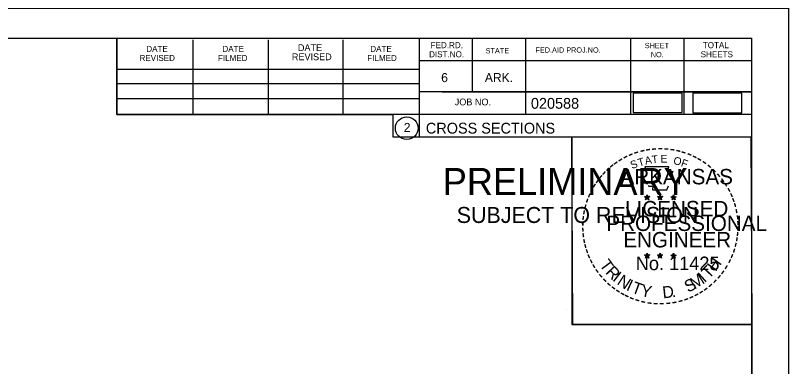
# Model space of a CAD drawing. Extents: x 1368968 to 1369915, y 377395 to 380381.
# Drawn here: x 1369814.5 to 1369914.7, y 378841.6 to 378887.1 of the extents above; entities that cross this region are included whole.
import ezdxf

# ---------------------------------------------------------------- set-up
doc = ezdxf.new("R2010")
doc.units = 0
for name, color, linetype in [('Default', 7, 'Continuous'), ('S_BRIDGE_ANNOT', 7, 'Continuous'), ('S_BUILDING_ANNOT', 7, 'Continuous'), ('S_CAL_CORNER', 7, 'Continuous'), ('S_DROP_INLET', 7, 'Continuous')]:
    doc.layers.add(name, color=color, linetype=linetype)

msp = doc.modelspace()

# ---------------------------------------------------------------- linework, layer by layer
at = {"layer": 'Default'}
for points in [[(1369894.57, 378874.54), (1369900.91, 378874.54), (1369900.91, 378877.06), (1369894.57, 378877.06)], [(1369902.32, 378874.51), (1369908.66, 378874.51), (1369908.66, 378877.03), (1369902.32, 378877.03)]]:
    msp.add_lwpolyline(points, close=True, dxfattribs=at)
at = {"layer": 'S_BRIDGE_ANNOT'}
for p, q in [((1369593.78, 378884.16), (1369909.96, 378884.16)), ((1369827.7, 378874.28), (1369827.7, 378884.16)), ((1369837.56, 378874.28), (1369837.56, 378883.96)), ((1369847.32, 378874.28), (1369847.32, 378883.96)), ((1369857, 378874.28), (1369857, 378883.96)), ((1369866.86, 378884.16), (1369866.86, 378871.36)), ((1369873.7, 378884.16), (1369873.7, 378877.22)), ((1369880.64, 378884.16), (1369880.64, 378874.28)), ((1369894.22, 378884.16), (1369894.22, 378874.28)), ((1369901.16, 378884.16), (1369901.16, 378874.28)), ((1369909.96, 378678.7), (1369909.96, 378884.16)), ((1369909.96, 378881.22), (1369866.86, 378881.22)), ((1369909.96, 378881.24), (1369909.96, 378881.24)), ((1369827.7, 378880.14), (1369866.86, 378880.14)), ((1369827.7, 378878.28), (1369866.86, 378878.28)), ((1369909.96, 378877.22), (1369866.86, 378877.22)), ((1369869.82, 378877.22), (1369909.96, 378877.22)), ((1369827.7, 378874.28), (1369827.7, 378876.34)), ((1369827.7, 378876.34), (1369866.86, 378876.34)), ((1369909.96, 378874.28), (1369827.7, 378874.28)), ((1369866.86, 378871.36), (1369909.96, 378871.36))]:
    msp.add_line(p, q, dxfattribs=at)
msp.add_circle((1369865.24, 378872.5), 1.47, dxfattribs=at)
at = {"layer": 'S_BUILDING_ANNOT'}
for p, q in [((1369896.04, 378863.62), (1369896.39, 378863.51)), ((1369896.04, 378863.62), (1369896.29, 378863.58)), ((1369896.04, 378863.62), (1369896.28, 378863.5)), ((1369896.17, 378863.21), (1369896.39, 378863.51)), ((1369896.39, 378863.87), (1369896.35, 378863.62)), ((1369896.39, 378863.51), (1369896.39, 378863.87)), ((1369896.39, 378863.87), (1369896.44, 378863.62)), ((1369896.74, 378863.62), (1369896.39, 378863.51)), ((1369896.6, 378863.21), (1369896.39, 378863.51)), ((1369896.74, 378863.62), (1369896.45, 378863.57)), ((1369896.6, 378863.21), (1369896.47, 378863.5)), ((1369896.74, 378863.62), (1369896.53, 378863.52)), ((1369897.71, 378863.62), (1369898.06, 378863.51)), ((1369897.71, 378863.62), (1369897.96, 378863.58)), ((1369897.71, 378863.62), (1369897.95, 378863.5)), ((1369897.84, 378863.21), (1369898.06, 378863.51)), ((1369898.06, 378863.87), (1369898.02, 378863.62)), ((1369898.06, 378863.51), (1369898.06, 378863.87)), ((1369898.06, 378863.87), (1369898.11, 378863.62)), ((1369898.41, 378863.62), (1369898.06, 378863.51)), ((1369898.27, 378863.21), (1369898.06, 378863.51)), ((1369898.41, 378863.62), (1369898.12, 378863.57)), ((1369898.27, 378863.21), (1369898.14, 378863.5)), ((1369898.41, 378863.62), (1369898.2, 378863.52)), ((1369899.48, 378863.61), (1369899.82, 378863.5)), ((1369899.48, 378863.61), (1369899.73, 378863.56)), ((1369899.48, 378863.61), (1369899.71, 378863.49)), ((1369899.61, 378863.2), (1369899.82, 378863.5)), ((1369899.82, 378863.86), (1369899.78, 378863.61)), ((1369899.82, 378863.5), (1369899.82, 378863.86)), ((1369899.82, 378863.86), (1369899.87, 378863.61)), ((1369900.17, 378863.61), (1369899.82, 378863.5)), ((1369900.04, 378863.2), (1369899.82, 378863.5)), ((1369900.17, 378863.61), (1369899.89, 378863.56)), ((1369900.04, 378863.2), (1369899.9, 378863.49)), ((1369900.17, 378863.61), (1369899.97, 378863.51)), ((1369896.17, 378863.21), (1369896.3, 378863.46)), ((1369896.17, 378863.21), (1369896.39, 378863.43)), ((1369896.6, 378863.21), (1369896.39, 378863.43)), ((1369897.84, 378863.21), (1369897.97, 378863.46)), ((1369897.84, 378863.21), (1369898.06, 378863.43)), ((1369898.27, 378863.21), (1369898.06, 378863.43)), ((1369899.61, 378863.2), (1369899.73, 378863.44)), ((1369899.61, 378863.2), (1369899.82, 378863.42)), ((1369900.04, 378863.2), (1369899.82, 378863.41)), ((1369896.04, 378856.05), (1369896.39, 378855.94)), ((1369896.04, 378856.05), (1369896.29, 378856)), ((1369896.04, 378856.05), (1369896.27, 378855.93)), ((1369896.17, 378855.64), (1369896.39, 378855.94)), ((1369896.17, 378855.64), (1369896.3, 378855.88)), ((1369896.17, 378855.64), (1369896.38, 378855.86)), ((1369896.39, 378856.3), (1369896.35, 378856.05)), ((1369896.6, 378855.64), (1369896.38, 378855.85)), ((1369896.39, 378855.94), (1369896.39, 378856.3)), ((1369896.39, 378856.3), (1369896.44, 378856.05)), ((1369896.73, 378856.05), (1369896.39, 378855.94)), ((1369896.6, 378855.64), (1369896.39, 378855.94)), ((1369896.73, 378856.05), (1369896.45, 378856)), ((1369896.6, 378855.64), (1369896.46, 378855.93)), ((1369896.73, 378856.05), (1369896.53, 378855.95)), ((1369897.71, 378856.05), (1369898.06, 378855.94)), ((1369897.71, 378856.05), (1369897.96, 378856)), ((1369897.71, 378856.05), (1369897.94, 378855.93)), ((1369897.84, 378855.64), (1369898.06, 378855.94)), ((1369897.84, 378855.64), (1369897.97, 378855.88)), ((1369897.84, 378855.64), (1369898.05, 378855.86)), ((1369898.06, 378856.3), (1369898.01, 378856.05)), ((1369898.27, 378855.64), (1369898.05, 378855.85)), ((1369898.06, 378855.94), (1369898.06, 378856.3)), ((1369898.06, 378856.3), (1369898.1, 378856.05)), ((1369898.4, 378856.05), (1369898.06, 378855.94)), ((1369898.27, 378855.64), (1369898.06, 378855.94)), ((1369898.4, 378856.05), (1369898.12, 378856)), ((1369898.27, 378855.64), (1369898.13, 378855.93)), ((1369898.4, 378856.05), (1369898.2, 378855.95)), ((1369899.47, 378856.04), (1369899.82, 378855.93)), ((1369899.47, 378856.04), (1369899.73, 378855.99)), ((1369899.47, 378856.04), (1369899.71, 378855.92)), ((1369899.61, 378855.63), (1369899.82, 378855.93)), ((1369899.61, 378855.63), (1369899.73, 378855.87)), ((1369899.61, 378855.63), (1369899.82, 378855.85)), ((1369899.82, 378856.29), (1369899.78, 378856.04)), ((1369899.82, 378855.93), (1369899.82, 378856.29)), ((1369899.82, 378856.29), (1369899.87, 378856.04)), ((1369900.17, 378856.04), (1369899.82, 378855.93)), ((1369900.04, 378855.63), (1369899.82, 378855.93)), ((1369900.04, 378855.63), (1369899.82, 378855.84)), ((1369900.17, 378856.04), (1369899.88, 378855.99)), ((1369900.04, 378855.63), (1369899.9, 378855.92)), ((1369900.17, 378856.04), (1369899.97, 378855.94))]:
    msp.add_line(p, q, dxfattribs=at)
for points in [[(1369896.08, 378867.5), (1369896.35, 378866.67)], [(1369899.59, 378866.58), (1369899.74, 378866.86), (1369899.05, 378866.84), (1369899.2, 378867.5), (1369896.08, 378867.5)], [(1369896.57, 378865.08), (1369896.57, 378864.99), (1369897.14, 378864.97), (1369897.08, 378864.5), (1369898.95, 378864.5), (1369899.15, 378865.03)], [(1369896.39, 378863.87), (1369896.6, 378863.21), (1369896.04, 378863.62), (1369896.74, 378863.62), (1369896.17, 378863.21), (1369896.39, 378863.87)], [(1369898.06, 378863.87), (1369898.27, 378863.21), (1369897.71, 378863.62), (1369898.41, 378863.62), (1369897.84, 378863.21), (1369898.06, 378863.87)], [(1369899.82, 378863.86), (1369900.04, 378863.2), (1369899.48, 378863.61), (1369900.17, 378863.61), (1369899.61, 378863.2), (1369899.82, 378863.86)], [(1369896.39, 378856.3), (1369896.6, 378855.64), (1369896.04, 378856.05), (1369896.73, 378856.05), (1369896.17, 378855.64), (1369896.39, 378856.3)], [(1369898.06, 378856.3), (1369898.27, 378855.64), (1369897.71, 378856.05), (1369898.4, 378856.05), (1369897.84, 378855.64), (1369898.06, 378856.3)], [(1369899.82, 378856.29), (1369900.04, 378855.63), (1369899.47, 378856.04), (1369900.17, 378856.04), (1369899.61, 378855.63), (1369899.82, 378856.29)]]:
    msp.add_lwpolyline(points, dxfattribs=at)
for centre, radius in [((1369896.39, 378863.51), 0.172), ((1369896.39, 378863.51), 0.145), ((1369896.39, 378863.51), 0.116), ((1369896.39, 378863.51), 0.0991), ((1369896.39, 378863.51), 0.0747), ((1369896.39, 378863.51), 0.0495), ((1369896.39, 378863.51), 0.0296), ((1369898.06, 378863.51), 0.172), ((1369898.06, 378863.51), 0.145), ((1369898.06, 378863.51), 0.116), ((1369898.06, 378863.51), 0.0991), ((1369898.06, 378863.51), 0.0747), ((1369898.06, 378863.51), 0.0495), ((1369898.06, 378863.51), 0.0296), ((1369899.82, 378863.5), 0.172), ((1369899.82, 378863.5), 0.145), ((1369899.82, 378863.5), 0.116), ((1369899.82, 378863.5), 0.0991), ((1369899.82, 378863.5), 0.0747), ((1369899.82, 378863.5), 0.0495), ((1369899.82, 378863.5), 0.0296), ((1369896.39, 378855.94), 0.172), ((1369896.39, 378855.94), 0.145), ((1369896.39, 378855.94), 0.116), ((1369896.39, 378855.94), 0.0991), ((1369896.39, 378855.94), 0.0747), ((1369896.39, 378855.94), 0.0495), ((1369896.39, 378855.94), 0.0296), ((1369898.05, 378855.94), 0.172), ((1369898.05, 378855.94), 0.145), ((1369898.05, 378855.94), 0.116), ((1369898.05, 378855.94), 0.0991), ((1369898.05, 378855.94), 0.0747), ((1369898.05, 378855.94), 0.0495), ((1369898.05, 378855.94), 0.0296), ((1369899.82, 378855.93), 0.172), ((1369899.82, 378855.93), 0.145), ((1369899.82, 378855.93), 0.116), ((1369899.82, 378855.93), 0.0991), ((1369899.82, 378855.93), 0.0747), ((1369899.82, 378855.93), 0.0495), ((1369899.82, 378855.93), 0.0296)]:
    msp.add_circle(centre, radius, dxfattribs=at)
at = {"layer": 'S_DROP_INLET'}
msp.add_line((1369885.99, 378848.91), (1369885.99, 378848.91), dxfattribs=at)
for points in [[(1369581.37, 378888.06), (1369914.71, 378888.06), (1369914.71, 378674.72), (1369581.37, 378674.72)], [(1369827.7, 378884.16), (1369827.7, 378874.28), (1369863.43, 378874.28), (1369863.43, 378871.36), (1369886.63, 378871.36), (1369886.63, 378847.03), (1369909.96, 378847.03), (1369909.96, 378678.7), (1369593.78, 378678.7), (1369593.78, 378884.16)], [(1369886.63, 378871.36), (1369909.84, 378871.36), (1369909.96, 378847.03), (1369886.75, 378847.03)]]:
    msp.add_lwpolyline(points, close=True, dxfattribs=at)

# ---------------------------------------------------------------- texts
at = {"layer": 'S_BRIDGE_ANNOT'}
for s, height, p in [('FED.RD.', 0.782, (1369868.34, 378882.88)), ('SHEET', 0.684, (1369896.08, 378882.88)), ('TOTAL', 0.782, (1369903.6, 378882.88)), ('DATE', 0.782, (1369831.5, 378882.4)), ('DATE', 0.782, (1369841.36, 378882.4)), ('DATE', 0.879, (1369851.14, 378882.5)), ('DATE', 0.782, (1369860.52, 378882.4)), ('DIST.NO.', 0.782, (1369868.14, 378881.7)), ('STATE', 0.684, (1369875.46, 378882.2)), ('FED.AID PROJ.NO.', 0.684, (1369881.92, 378882.3)), ('SHEETS', 0.782, (1369903.32, 378881.7)), ('REVISED', 0.782, (1369830.62, 378881.22)), ('FILMED', 0.782, (1369840.78, 378881.22)), ('REVISED', 0.879, (1369850.36, 378881.32)), ('FILMED', 0.782, (1369860.12, 378881.22)), ('NO.', 0.684, (1369896.86, 378881.7)), ('6', 1.17, (1369869.7, 378878.48)), ('ARK.', 1.172, (1369875.36, 378878.48)), ('JOB NO.', 0.879, (1369871.46, 378875.46)), ('020588', 1.4, (1369881.33, 378875.02)), ('2', 1.17, (1369864.86, 378872.01)), ('CROSS SECTIONS', 1.4, (1369867.72, 378871.8))]:
    msp.add_text(s, height=height, rotation=360, dxfattribs=at).set_placement(p)
at = {"layer": 'S_BUILDING_ANNOT'}
for s, height, rotation, p in [('-', 1.6, 19.1761, (1369894.83, 378868.63)), ('-', 1.6, 13.6301, (1369895.58, 378868.87)), ('-', 1.6, 10.2193, (1369896.26, 378869.03)), ('-', 1.6, 5.8968, (1369896.99, 378869.14)), ('-', 1.6, 0.1862, (1369897.76, 378869.21)), ('-', 1.6, 357.743, (1369898.48, 378869.2)), ('-', 1.6, 352.1617, (1369899.23, 378869.14)), ('-', 1.6, 347.2049, (1369899.95, 378869.03)), ('-', 1.6, 342.3362, (1369900.58, 378868.87)), ('-', 1.6, 34.0636, (1369892.97, 378867.67)), ('-', 1.6, 28.7918, (1369893.56, 378868.04)), ('-', 1.6, 24.3072, (1369894.2, 378868.36)), ('T', 1, 16.4036, (1369895.35, 378867.51)), ('A', 1, 11.2132, (1369896.18, 378867.76)), ('T', 1, 6.0228, (1369897.03, 378867.92)), ('E', 1, 0.8323, (1369898.13, 378868.03)), ('O', 1, 350.4515, (1369899.74, 378867.82)), ('F', 1, 340.0707, (1369900.69, 378867.6)), ('-', 1.6, 337.8551, (1369901.32, 378868.65)), ('-', 1.6, 334.1211, (1369901.95, 378868.38)), ('-', 1.6, 329.6409, (1369902.53, 378868.1)), ('-', 1.6, 38.9507, (1369891.91, 378866.9)), ('-', 1.6, 36.2317, (1369892.39, 378867.27)), ('S', 1, 21.594, (1369894.44, 378867.18)), ('-', 1.6, 325.8627, (1369903.17, 378867.73)), ('-', 1.6, 320.5297, (1369903.78, 378867.31)), ('-', 1.6, 48.423, (1369891.03, 378866)), ('-', 1.6, 42.9622, (1369891.48, 378866.48)), ('ARKANSAS', 2, 360, (1369892.94, 378865.21)), ('-', 1.6, 315.5786, (1369904.38, 378866.82)), ('-', 1.6, 309.8797, (1369904.95, 378866.27)), ('-', 1.6, 54.2325, (1369890.22, 378864.95)), ('-', 1.6, 50.6142, (1369890.63, 378865.52)), ('-', 1.6, 306.6522, (1369905.47, 378865.67)), ('-', 1.6, 62.8713, (1369889.58, 378863.81)), ('-', 1.6, 58.0706, (1369889.89, 378864.42)), ('-', 1.4, 303.6753, (1369905.96, 378865.1)), ('-', 1.6, 299.6684, (1369906.28, 378864.49)), ('-', 1.6, 67.7743, (1369889.32, 378863.2)), ('DWB', 0.01, 360, (1369896.38, 378863.5)), ('DWB', 0.01, 360, (1369898.05, 378863.5)), ('DWB', 0.01, 360, (1369899.81, 378863.49)), ('-', 1.6, 294.6628, (1369906.6, 378863.88)), ('-', 1.6, 290.5728, (1369906.86, 378863.3)), ('-', 1.6, 75.461, (1369888.9, 378861.85)), ('-', 1.6, 72.3945, (1369889.1, 378862.57)), ('LICENSED', 2, 360, (1369893.53, 378861.06)), ('-', 1.6, 285.1233, (1369907.09, 378862.72)), ('-', 1.6, 81.2013, (1369888.77, 378861.14)), ('-', 1.6, 280.5493, (1369907.29, 378861.98)), ('-', 1.6, 85.1863, (1369888.69, 378860.45)), ('PROFESSIONAL', 2, 360, (1369891.11, 378859.16)), ('-', 1.6, 276.5962, (1369907.45, 378861.21)), ('-', 1.6, 94.1959, (1369888.7, 378859.02)), ('-', 1.6, 89.0622, (1369888.67, 378859.75)), ('-', 1.6, 274.3301, (1369907.51, 378860.49)), ('-', 1.6, 269.9407, (1369907.55, 378859.86)), ('-', 1.6, 98.9479, (1369888.78, 378858.36)), ('ENGINEER', 2, 360, (1369893.3, 378857.03)), ('-', 1.6, 263.5172, (1369907.53, 378859.19)), ('-', 1.6, 101.7149, (1369888.91, 378857.62)), ('-', 1.6, 105.4578, (1369889.07, 378857.03)), ('-', 1.6, 255.7626, (1369907.35, 378857.86)), ('-', 1.6, 260.9953, (1369907.46, 378858.54)), ('-', 1.6, 109.0874, (1369889.29, 378856.4)), ('-', 1.6, 252.8681, (1369907.17, 378857.14)), ('-', 1.6, 114.0643, (1369889.54, 378855.8)), ('-', 1.6, 115.7289, (1369889.85, 378855.18)), ('T', 1.54, 306.0406, (1369890.15, 378854.77)), ('No. 11425', 1.757, 360, (1369894.92, 378854.08)), ('DWB', 0.01, 360, (1369896.37, 378855.93)), ('DWB', 0.01, 360, (1369898.04, 378855.93)), ('DWB', 0.01, 360, (1369899.81, 378855.92)), ('H', 1.54, 54.6088, (1369905.27, 378853.81)), ('-', 1.6, 244.6197, (1369906.68, 378855.84)), ('-', 1.6, 247.8887, (1369906.94, 378856.47)), ('-', 1.6, 120.4471, (1369890.2, 378854.6)), ('R', 1.54, 314.005, (1369890.91, 378853.73)), ('T', 1.54, 46.6444, (1369904.38, 378852.87)), ('-', 1.6, 239.0712, (1369906.29, 378855.09)), ('-', 1.6, 125.8934, (1369890.61, 378854.04)), ('-', 1.6, 130.7181, (1369891.07, 378853.48)), ('I', 1.54, 321.9694, (1369891.81, 378852.79)), ('N', 1.54, 326.5002, (1369892.38, 378852.32)), ('M', 1.54, 32.6563, (1369902.53, 378851.54)), ('I', 1.54, 42.1136, (1369903.81, 378852.39)), ('-', 1.6, 231.2538, (1369905.46, 378853.87)), ('-', 1.6, 233.8452, (1369905.89, 378854.44)), ('-', 1.6, 134.2238, (1369891.59, 378852.94)), ('-', 1.6, 138.9338, (1369892.11, 378852.47)), ('I', 1.54, 335.3603, (1369893.58, 378851.54)), ('T', 1.54, 339.8912, (1369894.25, 378851.21)), ('S', 1.54, 26.9312, (1369901.69, 378851.14)), ('-', 1.6, 225.7653, (1369904.98, 378853.31)), ('-', 1.6, 144.6463, (1369892.67, 378852.07)), ('-', 1.6, 148.0898, (1369893.23, 378851.7)), ('Y', 1.54, 347.8556, (1369895.46, 378850.76)), ('D', 1.54, 6.3969, (1369898.45, 378850.41)), ('-', 1.6, 212.2491, (1369903.37, 378851.94)), ('-', 1.6, 215.7363, (1369903.91, 378852.32)), ('-', 1.6, 221.0851, (1369904.45, 378852.8)), ('-', 1.6, 151.5704, (1369893.81, 378851.37)), ('-', 1.6, 154.6002, (1369894.33, 378851.13)), ('-', 1.6, 158.5612, (1369894.95, 378850.87)), ('.', 1.54, 13.7642, (1369899.64, 378850.53)), ('-', 1.6, 200.7184, (1369901.57, 378851)), ('-', 1.6, 204.2516, (1369902.19, 378851.27)), ('-', 1.6, 207.3568, (1369902.81, 378851.59)), ('-', 1.6, 162.7983, (1369895.64, 378850.66)), ('-', 1.6, 167.5555, (1369896.36, 378850.49)), ('-', 1.6, 173.1155, (1369897.13, 378850.38)), ('-', 1.6, 176.5183, (1369897.88, 378850.33)), ('-', 1.6, 181.5918, (1369898.62, 378850.35)), ('-', 1.6, 185.8167, (1369899.43, 378850.43)), ('-', 1.6, 191.2858, (1369900.16, 378850.56)), ('-', 1.6, 195.4743, (1369900.89, 378850.76))]:
    msp.add_text(s, height=height, rotation=rotation, dxfattribs=at).set_placement(p)
at = {"layer": 'S_CAL_CORNER'}
for s, height, p in [('PRELIMINARY', 3.5, (1369869.91, 378863.83)), ('DWB', 0.01, (1369870.65, 378865.68)), ('SUBJECT TO REVISION', 2.0751, (1369871.72, 378860.2))]:
    msp.add_text(s, height=height, rotation=360, dxfattribs=at).set_placement(p)

doc.saveas('drawing.dxf')
